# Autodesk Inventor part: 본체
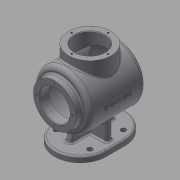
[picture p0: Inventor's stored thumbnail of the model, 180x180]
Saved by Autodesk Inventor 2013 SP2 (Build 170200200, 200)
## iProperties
Created: 2023-01
Part Number: 본체
Material: Generic
Document SubType Name: Modeling
Designer: aa
Density: 1 g/cm^3
Author: aa
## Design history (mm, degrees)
sketch "스케치1"
  geometry: L1 (-63, 0)-(59, 0); L2 (-63, 0)-(-63, 38); L3 (-63, 38)-(-51, 38); L4 (-51, 38)-(-51, 50); L5 (-51, 50)-(48.087, 50); L6 (-63, 27)-(-46, 27); L7 (-46, 27)-(-46, 45); L8 (-46, 45)-(44.83, 45); A1 r 120 centre (-61, 0) between (59, 0) and (48.087, 50); A2 r 115 centre (-61, 0) between (54, 0) and (44.83, 45); 2 further points
  constraints: 16 end point, 4 parallel, 4 point on circle, 3 perpendicular, 3 point on line, 2 centre point, 1 coincident, 1 horizontal, 1 horizontal alignment, 1 midpoint
  dimensions: "d0" = 122 distance of L1.start L1.end; "d1" = 120 radius of A1; "d2" = 76 diameter of L3 L1; "d3" = 100 diameter of L5 L1; "d4" = 12 distance of L2.end L3.end; "d5" = 5 radial gap between concentric circles of A1 A2; "d6" = 54 diameter of L6 L1; "d7" = 90 diameter of L8 L1; "d8" = 17 distance of L6.start L6.end; "d57" = 59 distance of L1.end point (0, 0)
revolve "회전1" sketch "스케치1" stored, may be unused: angle "d9" = 90 deg
fillet "모깎기1" dims "d10" = 8
fillet "모깎기2" dims "d11" = 3
fillet "모깎기3" dims "d12" = 3
chamfer "모따기1" distance "d13" = 1; stored, may be unused: second distance "d14" = 2, angle "d15" = 45 deg
sketch "스케치2"
  geometry: C1 r 38 at (0, 0) reference; 1 further point
  constraints: 1 vertical alignment
  dimensions: "d16" = 32.5 distance of C1.centre point (0, 32.5)
hole "구멍1" sketch "스케치2" at (0, 32.5) diameter "d17" = 3.242; stored, may be unused: countersink angle "d21" = 90 deg, drill point angle "d23" = 118 deg; dims "d18" = 8, "d19" = 4, "d20" = 2, "d22" = 10
fillet "모깎기4" dims "d27" = 3
node "작업 평면1"
sketch "스케치3"
  geometry: L1 (51, 42)-(51, -42) reference; C1 r 38 at (0, 0); 1 further point
  constraints: 1 centre point, 1 coincident
  dimensions: "d29" = 76 diameter of C1; "d30" = 51 distance from line of C1.centre L1
extrude "돌출1" join sketch "스케치3" stored distance "d31" = 10; taper "d32" = 0 deg
sketch "스케치4"
  geometry: C1 r 38 at (0, 0) reference; C2 r 27 at (0, 0); 1 further point
  constraints: 1 centre point, 1 coincident
  dimensions: "d33" = 54 diameter of C2
extrude "돌출2" cut sketch "스케치4" stored distance "d34" = 10; taper "d35" = 0 deg
chamfer "모따기2" distance "d36" = 1; stored, may be unused: second distance "d37" = 2, angle "d38" = 45 deg
sketch "스케치5"
  geometry: C1 r 38 at (0, 0) reference; 2 further points
  constraints: 1 vertical alignment
  dimensions: "d39" = 32.5 distance of C1.centre point (0, 32.5)
hole "구멍2" sketch "스케치5" at (0, 32.5) diameter "d40" = 3.242; stored, may be unused: countersink angle "d44" = 90 deg, drill point angle "d46" = 118 deg; dims "d41" = 8, "d42" = 4, "d43" = 2, "d45" = 10
fillet "모깎기5" dims "d50" = 3
node "작업 평면2"
sketch "스케치6"
  geometry: L1 (63, 38)-(63, -38) reference; L2 (17, -46)-(-17, -46); L3 (17, 46)-(-17, 46); A1 r 46 centre (17, 0) between (17, -46) and (17, 46); A2 r 46 centre (-17, 0) between (-17, 46) and (-17, -46); 1 further point
  constraints: 5 tangent, 4 end point, 4 point on circle, 2 centre point, 2 horizontal alignment
  dimensions: "d52" = 92 diameter of A1; "d53" = 92 diameter of A2; "d54" = 126 dimension on A2 A1
extrude "돌출3" join sketch "스케치6" distance "d55" = 10; taper "d56" = 0 deg
sketch "스케치7"
  geometry: 2 further points
  dimensions: "d58" = 30 horizontal distance of point (0, 0) point (-30, 30); "d59" = 30 horizontal distance of point (0, 0) point (-30, 30)
hole "구멍3" sketch "스케치7" at (-30, 30) diameter "d60" = 9; stored, may be unused: countersink angle "d64" = 90 deg, drill point angle "d66" = 118 deg; dims "d61" = 8, "d62" = 4, "d63" = 2, "d65" = 10
fillet "모깎기6" dims "d73" = 3
sketch "스케치8"
  geometry: L1 (-5, -35)-(5, -35); L2 (5, -35)-(5, 35); L3 (5, 35)-(-5, 35); L4 (-5, 35)-(-5, -35); L5 (-5, -35)-(5, 35); L6 (5, -35)-(-5, 35); 1 further point
  constraints: 12 end point, 2 midpoint, 2 parallel, 1 horizontal, 1 perpendicular
  dimensions: "d74" = 10 distance of L3.end L2.end; "d75" = 70 distance of L2.end L1.end
extrude "돌출4" join sketch "스케치8" stored distance "d76" = 10; taper "d77" = 0 deg
sketch "스케치9"
  geometry: L1 (-62, 27)-(-63, 28) reference; L2 (-63, 28)-(-63, 30.879) reference; L3 (-63, 30.879)-(-53, 30.879) reference; L4 (-53, 30.879)-(-52.026, 32.5) reference; L5 (-52.026, 32.5)-(-53, 34.121) reference; L6 (-53, 34.121)-(-63, 34.121) reference; L7 (-63, 34.121)-(-63, 38) reference; L8 (-63, 38)-(-54, 38) reference; L9 (-51, 41)-(-51, 42) reference; L10 (-43, 50)-(-41, 50) reference; L11 (-38, 53)-(-38, 64) reference; L12 (-38, 64)-(-34.121, 64) reference; L13 (-34.121, 64)-(-34.121, 54) reference; L14 (-34.121, 54)-(-32.5, 53.026) reference; L15 (-32.5, 53.026)-(-30.879, 54) reference; L16 (-30.879, 54)-(-30.879, 64) reference; L17 (-30.879, 64)-(-28, 64) reference; L18 (-28, 64)-(-27, 63) reference; L19 (-27, 63)-(-27, 45) reference; L20 (-27, 45)-(-43, 45) reference; L21 (-46, 42)-(-46, 27) reference; L22 (-46, 27)-(-62, 27) reference; L23 (-60, -70)-(-5, -70) reference; L24 (-5, -70)-(-5, -50) reference; L25 (-5, -50)-(-43, -50) reference; L26 (-51, -42)-(-51, -41) reference; L27 (-54, -38)-(-63, -38) reference; L28 (-63, -38)-(-63, -34.121) reference; L29 (-63, -34.121)-(-53, -34.121) reference; L30 (-53, -34.121)-(-52.026, -32.5) reference; L31 (-52.026, -32.5)-(-53, -30.879) reference; L32 (-53, -30.879)-(-63, -30.879) reference; L33 (-63, -30.879)-(-63, -28) reference; L34 (-63, -28)-(-62, -27) reference; L35 (-62, -27)-(-46, -27) reference; L36 (-46, -27)-(-46, -42) reference; L37 (-43, -45)-(42.827, -45) reference; L38 (42.827, 45)-(27, 45) reference; L39 (27, 45)-(27, 63) reference; L40 (27, 63)-(28, 64) reference; L41 (28, 64)-(30.879, 64) reference; L42 (30.879, 64)-(30.879, 54) reference; L43 (30.879, 54)-(32.5, 53.026) reference; L44 (32.5, 53.026)-(34.121, 54) reference; L45 (34.121, 54)-(34.121, 64) reference; L46 (34.121, 64)-(38, 64) reference; L47 (38, 64)-(38, 53) reference; L48 (41, 50)-(42.827, 50) reference; L49 (42.827, -50)-(5, -50) reference; L50 (5, -50)-(5, -70) reference; L51 (5, -70)-(60, -70) reference; L52 (63, -73)-(63, -80) reference; L53 (63, -80)-(-63, -80) reference; L54 (-63, -80)-(-63, -73) reference; L55 (-40, -70)-(-34.641, -50); A1 r 3 centre (-54, 41) between (-54, 38) and (-51, 41) reference; A2 r 8 centre (-43, 42) between (-43, 50) and (-51, 42) reference; A3 r 3 centre (-43, 42) between (-43, 45) and (-46, 42) reference; A4 r 3 centre (-60, -73) between (-60, -70) and (-63, -73) reference; A5 r 8 centre (-43, -42) between (-51, -42) and (-43, -50) reference; A6 r 3 centre (-54, -41) between (-51, -41) and (-54, -38) reference; A7 r 3 centre (-43, -42) between (-46, -42) and (-43, -45) reference; A8 r 3 centre (42.827, -42) between (42.827, -45) and (45.608, -43.125) reference; A9 r 115 centre (-61, 0) between (45.608, -43.125) and (45.608, 43.125) reference; A10 r 3 centre (42.827, 42) between (45.608, 43.125) and (42.827, 45) reference; A11 r 8 centre (42.827, 42) between (50.243, 45) and (42.827, 50) reference; A12 r 120 centre (-61, 0) between (50.243, -45) and (50.243, 45) reference; A13 r 8 centre (42.827, -42) between (42.827, -50) and (50.243, -45) reference; A14 r 3 centre (60, -73) between (63, -73) and (60, -70) reference; 1 further point
  constraints: 2 end point, 2 point on line, 2 other
  dimensions: "d78" = 23 distance from line of L55.start L54; "d79" = 105 deg angle of L55 L23
feature "리브1" sketch "스케치9" dims "d80" = 1, "d81" = 10, "d82" = 0, "d83" = 0, "d84" = 1, "d85" = 1
fillet "모깎기7" dims "d86" = 3
fillet "모깎기8" dims "d87" = 3
node "작업 평면3"
sketch "스케치10"
  geometry: L1 (-63, -38)-(-63, 38) reference; L2 (63, -80)-(17, -80) reference; 2 further points
  constraints: 1 other
  dimensions: "d89" = 63 distance from line of point (0, 0) L1; "d90" = 80 distance from line of L2 point (0, 0)
feature "엠보싱1" sketch "스케치10" dims "d91" = 0.5, "d92" = 0
node "솔리드1"
pattern_circular "원형 패턴1" dims angle "d25" = 360 deg
pattern_circular "원형 패턴2" dims angle "d48" = 360 deg
pattern_linear "직사각형 패턴1" dims "d69" = 60
mirror "대칭1"
node "절단 모서리 투영1"
other parameters: "d28" = 64
